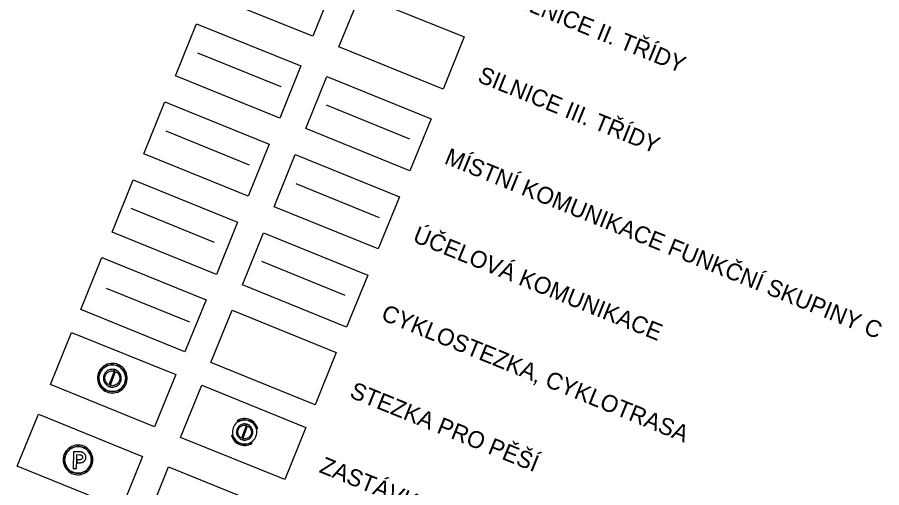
# Model space of a CAD drawing. Extents: x -522797 to -519326, y -1191143 to -1184078.
# Drawn here: x -522662 to -521893, y -1189651 to -1189233 of the extents above; entities that cross this region are included whole.
import ezdxf

# ---------------------------------------------------------------- set-up
doc = ezdxf.new("R2010")
doc.units = 0
for name, color, linetype in [('cyklostezka_s', 7, 'Continuous'), ('Implicitní', 7, 'Continuous'), ('ložisk_nerost', 7, 'Continuous'), ('MK_C_n', 7, 'Continuous'), ('stezka_s', 7, 'Continuous'), ('zast_HD_n', 7, 'Continuous'), ('zast_HD_s', 7, 'Continuous')]:
    doc.layers.add(name, color=color, linetype=linetype)

msp = doc.modelspace()

# ---------------------------------------------------------------- linework, layer by layer
at = {"layer": 'cyklostezka_s'}
msp.add_line((-522561.11, -1189402.42), (-522486.97, -1189432.47), dxfattribs=at)
at = {"layer": 'Implicitní'}
for p, q in [((-522501.76, -1189264.13), (-522427.61, -1189294.18)), ((-522529.93, -1189333.64), (-522455.78, -1189363.69)), ((-522414.34, -1189380.49), (-522340.2, -1189410.54)), ((-522444.92, -1189449.51), (-522370.78, -1189479.56))]:
    msp.add_line(p, q, dxfattribs=at)
for points in [[(-522473.12, -1189165.54), (-522380.44, -1189203.1), (-522399.22, -1189249.44), (-522491.9, -1189211.88)], [(-522357.27, -1189212.49), (-522264.59, -1189250.06), (-522283.37, -1189296.39), (-522376.05, -1189258.83)], [(-522502.58, -1189238.23), (-522409.9, -1189275.79), (-522428.68, -1189322.13), (-522521.36, -1189284.57)], [(-522386.73, -1189285.18), (-522294.05, -1189322.74), (-522312.83, -1189369.08), (-522405.51, -1189331.52)], [(-522530.75, -1189307.74), (-522438.07, -1189345.3), (-522456.85, -1189391.64), (-522549.53, -1189354.08)], [(-522414.9, -1189354.69), (-522322.22, -1189392.25), (-522341, -1189438.59), (-522433.68, -1189401.03)], [(-522558.92, -1189377.24), (-522466.24, -1189414.81), (-522485.02, -1189461.14), (-522577.7, -1189423.58)], [(-522443.07, -1189424.2), (-522350.39, -1189461.76), (-522369.17, -1189508.1), (-522461.85, -1189470.54)], [(-522586.86, -1189446.2), (-522494.19, -1189483.76), (-522512.97, -1189530.1), (-522605.64, -1189492.54)], [(-522471.02, -1189493.15), (-522378.34, -1189530.71), (-522397.12, -1189577.05), (-522489.8, -1189539.49)], [(-522613.86, -1189512.8), (-522521.18, -1189550.36), (-522539.96, -1189596.7), (-522632.64, -1189559.14)], [(-522498.01, -1189559.75), (-522405.33, -1189597.31), (-522424.11, -1189643.65), (-522516.79, -1189606.09)], [(-522643.3, -1189585.46), (-522550.63, -1189623.02), (-522569.41, -1189669.36), (-522662.08, -1189631.8)], [(-522527.46, -1189632.41), (-522434.78, -1189669.97), (-522453.56, -1189716.31), (-522546.24, -1189678.75)]]:
    msp.add_lwpolyline(points, close=True, dxfattribs=at)
at = {"layer": 'ložisk_nerost'}
for points in [[(-522607.78, -1189612.95), (-522608.88, -1189612.98), (-522610.54, -1189613.18), (-522612.15, -1189613.6), (-522613.71, -1189614.22), (-522615.17, -1189615.02), (-522616.52, -1189616.01), (-522617.73, -1189617.16), (-522618.79, -1189618.45), (-522619.67, -1189619.86), (-522620.38, -1189621.38), (-522620.88, -1189622.97), (-522621.18, -1189624.61), (-522621.27, -1189626.28), (-522621.15, -1189627.95), (-522620.82, -1189629.58), (-522620.28, -1189631.17), (-522619.55, -1189632.67), (-522618.64, -1189634.07), (-522617.56, -1189635.34), (-522616.32, -1189636.46), (-522614.96, -1189637.42), (-522613.48, -1189638.2), (-522611.92, -1189638.79), (-522610.29, -1189639.18), (-522608.63, -1189639.36), (-522606.96, -1189639.32), (-522605.31, -1189639.08), (-522603.7, -1189638.63), (-522602.16, -1189637.98), (-522600.72, -1189637.14), (-522599.39, -1189636.13), (-522598.21, -1189634.95), (-522597.17, -1189633.64), (-522596.32, -1189632.21), (-522595.65, -1189630.67), (-522595.18, -1189629.07), (-522594.91, -1189627.42), (-522594.86, -1189625.76), (-522595.02, -1189624.09), (-522595.38, -1189622.46), (-522595.95, -1189620.89), (-522596.71, -1189619.41), (-522597.65, -1189618.03), (-522598.76, -1189616.78), (-522600.02, -1189615.68), (-522601.41, -1189614.75), (-522602.9, -1189614), (-522604.47, -1189613.45), (-522606.11, -1189613.1), (-522607.77, -1189612.95)], [(-522596.18, -1189626.42), (-522596.24, -1189624.91), (-522596.49, -1189623.43), (-522596.93, -1189621.99), (-522597.54, -1189620.62), (-522598.32, -1189619.34), (-522599.26, -1189618.16), (-522600.34, -1189617.12), (-522601.54, -1189616.22), (-522602.85, -1189615.47), (-522604.24, -1189614.9), (-522605.69, -1189614.51), (-522607.18, -1189614.3), (-522608.68, -1189614.29), (-522610.17, -1189614.46), (-522611.63, -1189614.82), (-522613.04, -1189615.36), (-522614.36, -1189616.07), (-522615.58, -1189616.95), (-522616.68, -1189617.97), (-522617.65, -1189619.13), (-522618.46, -1189620.39), (-522619.1, -1189621.75), (-522619.57, -1189623.18), (-522619.85, -1189624.65), (-522619.95, -1189626.15), (-522619.86, -1189627.65), (-522619.57, -1189629.13), (-522619.11, -1189630.56), (-522618.46, -1189631.92), (-522617.65, -1189633.18), (-522616.69, -1189634.34), (-522615.59, -1189635.36), (-522614.37, -1189636.24), (-522613.05, -1189636.95), (-522611.64, -1189637.5), (-522610.19, -1189637.86), (-522608.69, -1189638.03), (-522607.19, -1189638.02), (-522605.7, -1189637.81), (-522604.25, -1189637.42), (-522602.86, -1189636.85), (-522601.55, -1189636.11), (-522600.35, -1189635.21), (-522599.27, -1189634.16), (-522598.33, -1189632.99), (-522597.55, -1189631.7), (-522596.93, -1189630.33), (-522596.49, -1189628.89), (-522596.24, -1189627.41), (-522596.18, -1189626.42)], [(-522607.8, -1189614.27), (-522606.81, -1189614.34), (-522605.33, -1189614.59), (-522603.89, -1189615.03), (-522602.52, -1189615.64), (-522601.24, -1189616.42), (-522600.06, -1189617.36), (-522599.02, -1189618.44), (-522598.12, -1189619.64), (-522597.37, -1189620.95), (-522596.8, -1189622.34), (-522596.41, -1189623.79), (-522596.2, -1189625.28), (-522596.19, -1189626.78), (-522596.36, -1189628.28), (-522596.72, -1189629.74), (-522597.27, -1189631.14), (-522597.98, -1189632.46), (-522598.86, -1189633.68), (-522599.88, -1189634.78), (-522601.03, -1189635.75), (-522602.3, -1189636.56), (-522603.66, -1189637.2), (-522605.08, -1189637.67), (-522606.56, -1189637.95), (-522608.06, -1189638.05), (-522609.56, -1189637.95), (-522611.04, -1189637.67), (-522612.47, -1189637.2), (-522613.82, -1189636.56), (-522615.09, -1189635.75), (-522616.24, -1189634.78), (-522617.27, -1189633.68), (-522618.14, -1189632.46), (-522618.86, -1189631.14), (-522619.4, -1189629.74), (-522619.76, -1189628.28), (-522619.93, -1189626.79), (-522619.92, -1189625.28), (-522619.71, -1189623.79), (-522619.32, -1189622.34), (-522618.75, -1189620.95), (-522618.01, -1189619.64), (-522617.11, -1189618.44), (-522616.06, -1189617.36), (-522614.89, -1189616.42), (-522613.6, -1189615.64), (-522612.23, -1189615.03), (-522610.79, -1189614.59), (-522609.31, -1189614.34), (-522607.81, -1189614.27)], [(-522605.74, -1189619.08), (-522612.19, -1189618.94), (-522612.51, -1189633.83), (-522609.34, -1189633.9), (-522609.17, -1189626.04)], [(-522607.81, -1189614.27), (-522607.78, -1189612.95)], [(-522607.77, -1189612.95), (-522607.8, -1189614.27)], [(-522605.95, -1189628.69), (-522605.24, -1189628.59), (-522604.77, -1189628.48), (-522604.42, -1189628.38), (-522604.06, -1189628.27), (-522603.82, -1189628.16), (-522603.59, -1189628.04), (-522603.23, -1189627.81), (-522602.87, -1189627.59), (-522602.63, -1189627.36), (-522602.39, -1189627.13), (-522602.15, -1189626.9), (-522601.91, -1189626.55), (-522601.67, -1189626.21), (-522601.55, -1189625.98), (-522601.43, -1189625.74), (-522601.3, -1189625.39), (-522601.18, -1189625.04), (-522601.05, -1189624.46), (-522601.04, -1189624.11), (-522601.03, -1189623.64), (-522601.13, -1189623.05), (-522601.13, -1189622.93), (-522601.24, -1189622.58), (-522601.35, -1189622.23), (-522601.58, -1189621.75), (-522601.8, -1189621.4), (-522602.03, -1189621.04), (-522602.26, -1189620.8), (-522602.49, -1189620.56), (-522602.72, -1189620.32), (-522603.06, -1189620.08), (-522603.41, -1189619.84), (-522603.64, -1189619.71), (-522603.87, -1189619.59), (-522604.22, -1189619.47), (-522604.45, -1189619.34), (-522605.04, -1189619.22), (-522605.74, -1189619.08)], [(-522609.12, -1189626.04), (-522609.18, -1189628.62)], [(-522609.17, -1189626.04), (-522609.07, -1189621.47)], [(-522606.59, -1189626.1), (-522609.12, -1189626.04)], [(-522609.07, -1189621.47), (-522606.5, -1189621.53)], [(-522606.5, -1189621.53), (-522606.38, -1189621.53), (-522606.26, -1189621.53), (-522605.68, -1189621.66), (-522605.45, -1189621.79), (-522605.21, -1189621.91), (-522604.98, -1189622.03), (-522604.75, -1189622.27), (-522604.52, -1189622.51), (-522604.3, -1189622.86), (-522604.19, -1189623.22), (-522604.08, -1189623.81), (-522604.09, -1189624.04), (-522604.21, -1189624.51), (-522604.34, -1189624.86), (-522604.58, -1189625.2), (-522604.7, -1189625.32), (-522604.94, -1189625.55), (-522605.3, -1189625.78), (-522605.54, -1189625.89), (-522605.89, -1189626), (-522606.36, -1189626.1), (-522606.59, -1189626.1)], [(-522609.18, -1189628.62), (-522605.95, -1189628.69)]]:
    msp.add_lwpolyline(points, dxfattribs=at)
at = {"layer": 'MK_C_n'}
msp.add_line((-522387.41, -1189310.47), (-522313.27, -1189340.52), dxfattribs=at)
at = {"layer": 'stezka_s'}
msp.add_line((-522582.91, -1189473.38), (-522508.77, -1189503.43), dxfattribs=at)
at = {"layer": 'zast_HD_n'}
msp.add_line((-522461.87, -1189608.29), (-522461.87, -1189608.29), dxfattribs=at)
for points in [[(-522449.79, -1189605.26), (-522449.38, -1189603.96), (-522449.14, -1189602.61), (-522449.07, -1189601.25), (-522449.17, -1189599.89), (-522449.45, -1189598.55), (-522449.89, -1189597.25), (-522450.49, -1189596.03), (-522451.24, -1189594.88), (-522452.13, -1189593.85), (-522453.14, -1189592.93), (-522454.26, -1189592.15), (-522455.47, -1189591.51), (-522456.75, -1189591.04), (-522458.08, -1189590.73), (-522459.44, -1189590.58), (-522460.81, -1189590.62), (-522462.16, -1189590.82), (-522463.48, -1189591.19), (-522464.73, -1189591.73), (-522465.91, -1189592.42), (-522466.99, -1189593.25), (-522467.96, -1189594.21), (-522468.8, -1189595.29), (-522469.5, -1189596.47), (-522470.05, -1189597.72), (-522470.43, -1189599.03), (-522470.64, -1189600.38), (-522470.68, -1189601.75), (-522470.55, -1189603.11), (-522470.24, -1189604.44), (-522469.77, -1189605.72), (-522469.15, -1189606.94), (-522468.37, -1189608.06), (-522467.46, -1189609.08), (-522466.43, -1189609.98), (-522465.29, -1189610.74), (-522464.07, -1189611.35), (-522462.78, -1189611.79), (-522461.44, -1189612.08), (-522460.08, -1189612.19), (-522458.72, -1189612.13), (-522457.37, -1189611.9), (-522456.06, -1189611.5), (-522454.82, -1189610.93), (-522453.65, -1189610.22), (-522452.59, -1189609.36), (-522451.64, -1189608.38), (-522450.82, -1189607.28), (-522450.15, -1189606.1), (-522449.79, -1189605.26)], [(-522457.9, -1189594.47), (-522458.78, -1189594.28), (-522459.69, -1189594.2), (-522460.6, -1189594.23), (-522461.49, -1189594.38), (-522462.37, -1189594.64), (-522463.2, -1189595), (-522463.98, -1189595.47), (-522464.69, -1189596.03), (-522465.33, -1189596.68), (-522465.87, -1189597.41), (-522466.33, -1189598.19), (-522466.68, -1189599.03), (-522466.92, -1189599.91), (-522467.05, -1189600.81), (-522467.06, -1189601.72), (-522466.97, -1189602.62), (-522466.75, -1189603.5), (-522466.43, -1189604.35), (-522466, -1189605.15), (-522465.48, -1189605.9), (-522464.86, -1189606.56), (-522464.17, -1189607.15), (-522463.41, -1189607.65), (-522462.59, -1189608.04), (-522461.92, -1189608.28)], [(-522455.58, -1189590.17), (-522456.29, -1189589.92), (-522457.76, -1189589.56), (-522459.27, -1189589.39), (-522460.79, -1189589.41), (-522462.29, -1189589.62), (-522463.76, -1189590.02), (-522465.16, -1189590.59), (-522466.48, -1189591.35)], [(-522466.48, -1189591.35), (-522465.06, -1189591.89)], [(-522462.58, -1189606.78), (-522463.24, -1189606.4), (-522463.85, -1189605.94), (-522464.39, -1189605.4), (-522464.86, -1189604.8), (-522465.25, -1189604.15), (-522465.56, -1189603.45), (-522465.77, -1189602.71), (-522465.89, -1189601.96), (-522465.92, -1189601.2), (-522465.85, -1189600.44), (-522465.68, -1189599.69), (-522465.42, -1189598.98), (-522465.07, -1189598.3), (-522464.64, -1189597.67), (-522464.14, -1189597.09), (-522463.56, -1189596.59), (-522462.93, -1189596.17), (-522462.25, -1189595.83), (-522461.53, -1189595.57), (-522460.78, -1189595.41), (-522460.02, -1189595.34), (-522459.26, -1189595.37), (-522458.5, -1189595.5), (-522458.31, -1189595.55)], [(-522465.06, -1189591.89), (-522464.02, -1189591.4), (-522462.73, -1189590.95), (-522461.39, -1189590.68), (-522460.03, -1189590.57), (-522458.66, -1189590.64), (-522457.32, -1189590.88), (-522456.01, -1189591.29)], [(-522457.85, -1189594.49), (-522462.58, -1189606.78)], [(-522461.92, -1189608.28), (-522457.19, -1189595.98)], [(-522461.87, -1189608.29), (-522460.98, -1189608.48), (-522460.08, -1189608.57), (-522459.17, -1189608.53), (-522458.28, -1189608.39), (-522457.41, -1189608.13), (-522456.57, -1189607.76), (-522455.8, -1189607.29), (-522455.08, -1189606.73), (-522454.45, -1189606.08), (-522453.9, -1189605.35), (-522453.44, -1189604.57), (-522453.09, -1189603.73), (-522452.85, -1189602.85), (-522452.72, -1189601.95), (-522452.71, -1189601.04), (-522452.8, -1189600.14), (-522453.02, -1189599.26), (-522453.34, -1189598.41), (-522453.77, -1189597.61), (-522454.29, -1189596.87), (-522454.91, -1189596.2), (-522455.6, -1189595.61), (-522456.36, -1189595.11), (-522457.18, -1189594.72), (-522457.85, -1189594.49)], [(-522457.19, -1189595.98), (-522456.53, -1189596.36), (-522455.92, -1189596.82), (-522455.38, -1189597.36), (-522454.91, -1189597.96), (-522454.52, -1189598.61), (-522454.21, -1189599.31), (-522454, -1189600.05), (-522453.88, -1189600.8), (-522453.85, -1189601.56), (-522453.92, -1189602.32), (-522454.09, -1189603.07), (-522454.35, -1189603.79), (-522454.7, -1189604.47), (-522455.13, -1189605.1), (-522455.63, -1189605.66), (-522456.21, -1189606.17), (-522456.84, -1189606.59), (-522457.52, -1189606.94), (-522458.24, -1189607.19), (-522458.99, -1189607.35), (-522459.75, -1189607.42), (-522460.51, -1189607.39), (-522461.26, -1189607.26), (-522461.46, -1189607.21)], [(-522458.31, -1189595.55), (-522457.9, -1189594.47)], [(-522456, -1189591.29), (-522454.95, -1189591.76), (-522453.78, -1189592.46), (-522452.7, -1189593.31), (-522451.74, -1189594.28), (-522450.91, -1189595.36), (-522450.22, -1189596.54), (-522449.69, -1189597.8)], [(-522448.27, -1189598.35), (-522448.48, -1189597.63), (-522449.04, -1189596.22), (-522449.78, -1189594.89), (-522450.68, -1189593.67), (-522451.73, -1189592.57), (-522452.9, -1189591.61), (-522454.19, -1189590.81), (-522455.57, -1189590.17)], [(-522449.69, -1189597.8), (-522448.27, -1189598.35)], [(-522471.5, -1189604.41), (-522471.03, -1189605.85), (-522470.38, -1189607.22), (-522469.56, -1189608.49), (-522468.58, -1189609.66), (-522467.47, -1189610.69), (-522466.24, -1189611.57), (-522464.9, -1189612.29), (-522463.48, -1189612.84), (-522462.01, -1189613.2), (-522460.5, -1189613.37), (-522458.98, -1189613.35), (-522457.48, -1189613.14), (-522456.01, -1189612.75), (-522454.61, -1189612.17), (-522453.29, -1189611.41)], [(-522470.08, -1189604.96), (-522471.5, -1189604.41)], [(-522454.71, -1189610.87), (-522455.56, -1189611.29), (-522456.85, -1189611.75), (-522458.18, -1189612.05), (-522459.54, -1189612.18), (-522460.91, -1189612.14), (-522462.26, -1189611.93), (-522463.57, -1189611.54), (-522464.82, -1189611), (-522465.99, -1189610.3), (-522467.07, -1189609.45), (-522468.03, -1189608.48), (-522468.86, -1189607.4), (-522469.55, -1189606.22), (-522470.08, -1189604.96)], [(-522461.46, -1189607.21), (-522461.87, -1189608.29)], [(-522453.29, -1189611.41), (-522454.71, -1189610.87)]]:
    msp.add_lwpolyline(points, dxfattribs=at)
at = {"layer": 'zast_HD_s'}
msp.add_line((-522579.75, -1189561.11), (-522579.75, -1189561.11), dxfattribs=at)
for points in [[(-522572.85, -1189541.18), (-522573.89, -1189540.83), (-522575.52, -1189540.46), (-522577.18, -1189540.31), (-522578.85, -1189540.37), (-522580.5, -1189540.63), (-522582.1, -1189541.11), (-522583.63, -1189541.78), (-522585.06, -1189542.64), (-522586.38, -1189543.67), (-522587.55, -1189544.86), (-522588.56, -1189546.19), (-522589.4, -1189547.63), (-522590.04, -1189549.17), (-522590.49, -1189550.78), (-522590.73, -1189552.43), (-522590.76, -1189554.1), (-522590.58, -1189555.76), (-522590.2, -1189557.39), (-522589.61, -1189558.95), (-522588.82, -1189560.42), (-522587.86, -1189561.79), (-522586.74, -1189563.02), (-522585.46, -1189564.1), (-522584.06, -1189565.01), (-522582.56, -1189565.74), (-522580.98, -1189566.27), (-522579.34, -1189566.6), (-522577.67, -1189566.72), (-522576.01, -1189566.63), (-522574.36, -1189566.33), (-522572.77, -1189565.82), (-522571.26, -1189565.12), (-522569.84, -1189564.23), (-522568.56, -1189563.17), (-522567.41, -1189561.95), (-522566.42, -1189560.6), (-522565.62, -1189559.14), (-522565, -1189557.59), (-522564.59, -1189555.97), (-522564.38, -1189554.31), (-522564.39, -1189552.64), (-522564.6, -1189550.99), (-522565.03, -1189549.37), (-522565.65, -1189547.82), (-522566.46, -1189546.36), (-522567.45, -1189545.02), (-522568.61, -1189543.81), (-522569.9, -1189542.76), (-522571.32, -1189541.88), (-522572.84, -1189541.18)], [(-522573.31, -1189542.41), (-522572.4, -1189542.81), (-522571.09, -1189543.54), (-522569.89, -1189544.44), (-522568.8, -1189545.48), (-522567.86, -1189546.65), (-522567.07, -1189547.93), (-522566.45, -1189549.3), (-522566.01, -1189550.74), (-522565.75, -1189552.22), (-522565.68, -1189553.72), (-522565.8, -1189555.22), (-522566.11, -1189556.69), (-522566.6, -1189558.11), (-522567.27, -1189559.45), (-522568.1, -1189560.71), (-522569.09, -1189561.84), (-522570.21, -1189562.85), (-522571.44, -1189563.7), (-522572.78, -1189564.39), (-522574.19, -1189564.91), (-522575.65, -1189565.25), (-522577.15, -1189565.39), (-522578.65, -1189565.35), (-522580.14, -1189565.12), (-522581.58, -1189564.7), (-522582.96, -1189564.11), (-522584.25, -1189563.34), (-522585.44, -1189562.42), (-522586.5, -1189561.36), (-522587.42, -1189560.17), (-522588.18, -1189558.87), (-522588.77, -1189557.49), (-522589.18, -1189556.04), (-522589.41, -1189554.56), (-522589.45, -1189553.05), (-522589.3, -1189551.56), (-522588.96, -1189550.1), (-522588.43, -1189548.69), (-522587.74, -1189547.35), (-522586.88, -1189546.12), (-522585.87, -1189545), (-522584.73, -1189544.02), (-522583.48, -1189543.2), (-522582.13, -1189542.53), (-522580.71, -1189542.05), (-522579.23, -1189541.74), (-522577.74, -1189541.62), (-522576.23, -1189541.7), (-522574.76, -1189541.96), (-522573.32, -1189542.41)], [(-522566.47, -1189557.77), (-522566.02, -1189556.33), (-522565.76, -1189554.85), (-522565.68, -1189553.35), (-522565.8, -1189551.85), (-522566.1, -1189550.38), (-522566.59, -1189548.96), (-522567.25, -1189547.61), (-522568.08, -1189546.35), (-522569.06, -1189545.21), (-522570.17, -1189544.21), (-522571.4, -1189543.35), (-522572.74, -1189542.65), (-522574.15, -1189542.13), (-522575.61, -1189541.79), (-522577.1, -1189541.63), (-522578.61, -1189541.67), (-522580.09, -1189541.9), (-522581.54, -1189542.31), (-522582.92, -1189542.9), (-522584.22, -1189543.66), (-522585.41, -1189544.58), (-522586.47, -1189545.64), (-522587.4, -1189546.82), (-522588.16, -1189548.12), (-522588.76, -1189549.49), (-522589.18, -1189550.94), (-522589.41, -1189552.42), (-522589.45, -1189553.93), (-522589.3, -1189555.42), (-522588.97, -1189556.89), (-522588.45, -1189558.3), (-522587.76, -1189559.63), (-522586.91, -1189560.87), (-522585.9, -1189561.99), (-522584.77, -1189562.97), (-522583.52, -1189563.81), (-522582.17, -1189564.48), (-522580.75, -1189564.97), (-522579.28, -1189565.28), (-522577.78, -1189565.4), (-522576.28, -1189565.33), (-522574.8, -1189565.07), (-522573.36, -1189564.63), (-522571.99, -1189564.01), (-522570.71, -1189563.22), (-522569.54, -1189562.28), (-522568.5, -1189561.2), (-522567.6, -1189559.99), (-522566.86, -1189558.68), (-522566.47, -1189557.77)], [(-522573.32, -1189542.41), (-522572.85, -1189541.18)], [(-522572.84, -1189541.18), (-522573.31, -1189542.41)], [(-522575.39, -1189545.91), (-522576.37, -1189545.7), (-522577.36, -1189545.61), (-522578.36, -1189545.65), (-522579.35, -1189545.81), (-522580.3, -1189546.1), (-522581.22, -1189546.5), (-522582.07, -1189547.02), (-522582.86, -1189547.64), (-522583.56, -1189548.35), (-522584.16, -1189549.15), (-522584.66, -1189550.02), (-522585.04, -1189550.94), (-522585.31, -1189551.9), (-522585.45, -1189552.89), (-522585.46, -1189553.89), (-522585.36, -1189554.88), (-522585.12, -1189555.85), (-522584.76, -1189556.79), (-522584.29, -1189557.67), (-522583.71, -1189558.49), (-522583.04, -1189559.22), (-522582.27, -1189559.87), (-522581.43, -1189560.41), (-522580.53, -1189560.84), (-522579.8, -1189561.1)], [(-522580.52, -1189559.46), (-522581.25, -1189559.04), (-522581.92, -1189558.53), (-522582.52, -1189557.94), (-522583.04, -1189557.28), (-522583.47, -1189556.56), (-522583.8, -1189555.79), (-522584.04, -1189554.99), (-522584.18, -1189554.16), (-522584.21, -1189553.32), (-522584.13, -1189552.48), (-522583.95, -1189551.66), (-522583.66, -1189550.87), (-522583.28, -1189550.13), (-522582.81, -1189549.43), (-522582.25, -1189548.8), (-522581.62, -1189548.25), (-522580.92, -1189547.78), (-522580.17, -1189547.4), (-522579.38, -1189547.12), (-522578.56, -1189546.95), (-522577.72, -1189546.87), (-522576.89, -1189546.91), (-522576.06, -1189547.05), (-522575.84, -1189547.1)], [(-522575.34, -1189545.93), (-522580.52, -1189559.46)], [(-522579.8, -1189561.1), (-522574.61, -1189547.56)], [(-522579.75, -1189561.11), (-522578.77, -1189561.33), (-522577.78, -1189561.42), (-522576.78, -1189561.38), (-522575.79, -1189561.22), (-522574.83, -1189560.93), (-522573.92, -1189560.53), (-522573.06, -1189560.01), (-522572.28, -1189559.39), (-522571.58, -1189558.67), (-522570.98, -1189557.88), (-522570.48, -1189557.01), (-522570.09, -1189556.09), (-522569.83, -1189555.12), (-522569.69, -1189554.13), (-522569.67, -1189553.13), (-522569.78, -1189552.14), (-522570.02, -1189551.17), (-522570.37, -1189550.24), (-522570.84, -1189549.36), (-522571.42, -1189548.54), (-522572.1, -1189547.8), (-522572.86, -1189547.16), (-522573.7, -1189546.62), (-522574.6, -1189546.18), (-522575.34, -1189545.93)], [(-522574.61, -1189547.56), (-522573.89, -1189547.99), (-522573.22, -1189548.49), (-522572.62, -1189549.08), (-522572.1, -1189549.74), (-522571.67, -1189550.46), (-522571.33, -1189551.23), (-522571.09, -1189552.04), (-522570.96, -1189552.87), (-522570.93, -1189553.7), (-522571.01, -1189554.54), (-522571.19, -1189555.36), (-522571.47, -1189556.15), (-522571.86, -1189556.9), (-522572.33, -1189557.59), (-522572.88, -1189558.22), (-522573.52, -1189558.77), (-522574.21, -1189559.24), (-522574.96, -1189559.62), (-522575.75, -1189559.9), (-522576.57, -1189560.08), (-522577.41, -1189560.15), (-522578.25, -1189560.12), (-522579.08, -1189559.98), (-522579.29, -1189559.93)], [(-522575.84, -1189547.1), (-522575.39, -1189545.91)], [(-522579.29, -1189559.93), (-522579.75, -1189561.11)]]:
    msp.add_lwpolyline(points, dxfattribs=at)

# ---------------------------------------------------------------- texts
at = {"layer": 'Implicitní'}
for s, p in [('SILNICE II. TŘÍDY', (-522225.46, -1189220.06)), ('SILNICE III. TŘÍDY', (-522253.63, -1189289.57)), ('MÍSTNÍ KOMUNIKACE FUNKČNÍ SKUPINY C', (-522283.09, -1189362.25)), ('ÚČELOVÁ KOMUNIKACE', (-522311.26, -1189431.76)), ('CYKLOSTEZKA, CYKLOTRASA ', (-522339.43, -1189501.27)), ('STEZKA PRO PĚŠÍ', (-522367.38, -1189570.22)), ('ZASTÁVKA HROMADNÉ DOPRAVY OSOB', (-522394.37, -1189636.82))]:
    msp.add_text(s, height=15, rotation=337.93793, dxfattribs=at).set_placement(p)

doc.saveas('drawing.dxf')
